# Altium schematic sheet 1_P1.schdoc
size 307 x 218 mm; Symbol: Sheet-Symbol_A4; Device: Sheet-Symbol_A4; Company: 嘉立创EDA; Version: V1.0; Page Size: A4; @Project Name: FOC12; @Page Count: 1; @Update Date: 2025-04-03; @Create Date: 2025-02-02; @Schematic Name: Schematic3; @Page No: 1; @Page Name: P1; @Board Name: SPI编码器板; @Create Time: 08:19:33; @Update Time: 16:03:33; Width: 1170; Height: 825; Region Start: 1; X Region Count: 6; Y Region Count: 4; Blade Width: 10; Title Block Position: 3
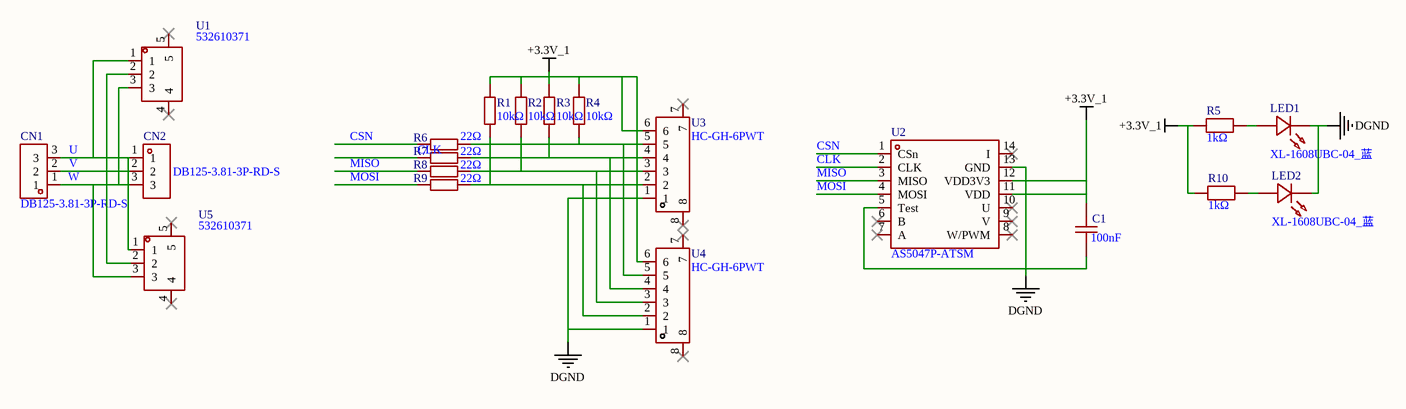
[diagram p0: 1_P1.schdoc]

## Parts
C1  100nF  [C0603]
CN1  DB125-3.81-3P-RD-S  [CONN-TH_3P-P3.81_L7.4-W11.4]
CN2  DB125-3.81-3P-RD-S  [CONN-TH_3P-P3.81_L7.4-W11.4]
LED1  XL-1608UBC-04_蓝  [LED0603-RD_BLUE]
LED2  XL-1608UBC-04_蓝  [LED0603-RD_BLUE]
R1  10kΩ  [R0402]
R2  10kΩ  [R0402]
R3  10kΩ  [R0402]
R4  10kΩ  [R0402]
R5  1kΩ  [R0402]
R6  22Ω  [R0603]
R7  22Ω  [R0603]
R8  22Ω  [R0603]
R9  22Ω  [R0603]
R10  1kΩ  [R0402]
U1  532610371  [CONN-TH_532610371]
U2  AS5047P-ATSM  [TSSOP-14_L5.0-W4.4-P0.65-LS6.4-BL]
U3  HC-GH-6PWT  [CONN-SMD_6P-P1.25_HCTL_HC-GH-6PWT]
U4  HC-GH-6PWT  [CONN-SMD_6P-P1.25_HCTL_HC-GH-6PWT]
U5  532610371  [CONN-TH_532610371]

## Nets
+3.3V_1: C1.2 R1.1 R2.1 R3.2 R4.1 R5.2 R10.2 U2.11(VDD) U2.12(VDD3V3) U3.6 U4.6
DGND: C1.1 LED1.1(K) LED2.1(K) U2.5(Test) U2.13(GND) U3.1 U4.1
CLK: R7.1 U2.2(CLK)
CSN: R6.1 U2.1(CSn)
MISO: R8.1 U2.3(MISO)
MOSI: R9.1 U2.4(MOSI)
U: CN1.3 CN2.1 U1.1 U5.1
V: CN1.2 CN2.2 U1.2 U5.2
W: CN1.1 CN2.3 U1.3 U5.3
NetLED1_2: LED1.2(A) R5.1
NetLED2_2: LED2.2(A) R10.1
NetR1_2: R1.2 R9.2 U3.2 U4.2
NetR2_2: R2.2 R8.2 U3.3 U4.3
NetR3_1: R3.1 R7.2 U3.4 U4.4
NetR4_2: R4.2 R6.2 U3.5 U4.5

Not connected (* = marked no-connect by the designer): U1 4* 5*; U2 6(B)* 7(A)* 8(W/PWM)* 9(V)* 10(U)* 14(I)*; U3 7* 8*; U4 7* 8*; U5 4* 5*

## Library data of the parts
C1 = CGA0603X7R104K500JT: Manufacturer: HRE(芯声); Add into BOM: yes; Tolerance: ±10%; Voltage Rated: 50V; Temperature Coefficient: X7R
CN1 CN2 = DB125-3.81-3P-RD-S: Manufacturer: DIBO(地博电气); Add into BOM: yes; Pitch: 3.81mm; Number of PINs Per Row: 3; Current Rating (Max): 10A; Voltage Rating (Max): 300V; Wire Gauge - AWG: 16~26; Wire Gauge - mm2: 0.5~1
LED1 LED2 = XL-1608UBC-04: Manufacturer: XINGLIGHT(成兴光); Add into BOM: yes; Emitted Color: 蓝色; Power Dissipation: 80mW; Forward Current: 25mA; Dominant Wavelength: 460nm~469nm; Peak Wavelength: 475nm; Lens Color: 无色透明透镜; Viewing Angle: 120°; Mounting Sytle: 正贴
R1-R4 = 0402WGF1002TCE: Manufacturer: UNI-ROYAL(厚声); Add into BOM: yes; Tolerance: ±1%; Power(Watts): 62.5mW; Overload Voltage (Max): 50V; Temperature Coefficient: ±100ppm/℃
R5 R10 = FRC0402J102 TS: Manufacturer: FOJAN(富捷); Add into BOM: yes; Tolerance: ±5%; Power(Watts): 62.5mW; Overload Voltage (Max): 50V; Temperature Coefficient: ±100ppm/℃
R6-R9 = 0603WAF220JT5E: Manufacturer: UNI-ROYAL(厚声); Add into BOM: yes; Tolerance: ±1%; Power(Watts): 100mW; Overload Voltage (Max): 75V; Temperature Coefficient: ±100ppm/℃
U1 U5 = 532610371: Manufacturer: MOLEX; Add into BOM: yes; Pins Structure: 1x3P; Pitch: 1.25mm; Number of PINs Per Row: 3
U2 = AS5047P-ATSM_C962063: Manufacturer: ams(艾迈斯半导体); Add into BOM: yes
U3 U4 = HC-GH-6PWT: Manufacturer: HCTL(华灿天禄); Symbol: HC-GH-6PWTKK; Add into BOM: yes; Pins Structure: 1x6P; Pitch: 1.25mm; Reference Series: GH; Number of PINs Per Row: 6; Current Rating (Max): 1A; Rated Voltage (Max): 50V; Plastic Material: LCP; Flame Retardant Rating: UL94V-0; Supplementary Features: 辅助焊脚; Z-Height of the Board: 4.25mm; X-Length of Bottom Edge on Board (Spacing Line): 10.75mm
